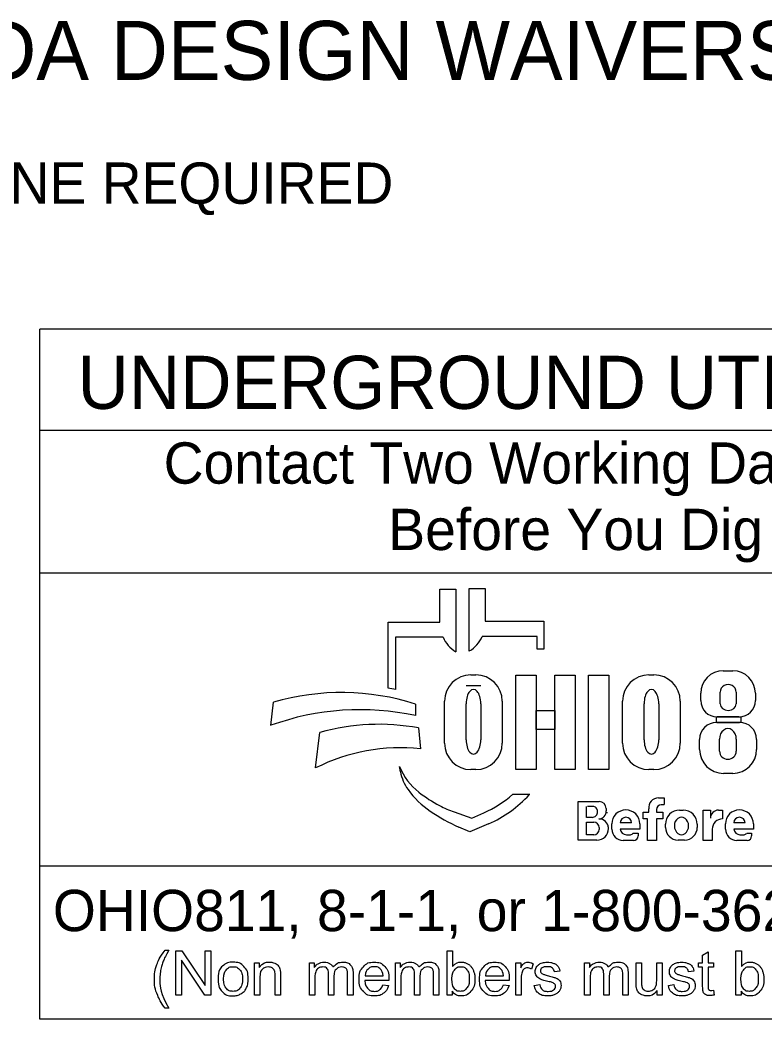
# Model space of a CAD drawing. Extents: x 0 to 44.3, y 0 to 22.
# Drawn here: x 2.311 to 4.831, y 2.143 to 5.529 of the extents above; entities that cross this region are included whole.
import ezdxf

# ---------------------------------------------------------------- set-up
doc = ezdxf.new("R2010")
doc.units = 0
doc.layers.add('SH_Data', color=7, linetype='Continuous')
doc.layers.add('SH_Text', color=7, linetype='Continuous')

msp = doc.modelspace()

# ---------------------------------------------------------------- linework, layer by layer
at = {"layer": 'SH_Data'}
for p, q in [((2.3775, 2.1428), (2.3775, 4.4803)), ((6.6275, 4.4803), (2.3775, 4.4803)), ((2.3775, 4.1387), (6.6275, 4.1387)), ((2.3775, 3.6553), (6.6275, 3.6553)), ((6.6275, 2.6607), (2.3775, 2.6607)), ((6.6275, 2.1428), (2.3775, 2.1428))]:
    msp.add_line(p, q, dxfattribs=at)
at = {"layer": 'SH_Text'}
for p, q in [((3.7335, 3.4883), (3.7335, 3.5998)), ((3.7335, 3.5998), (3.7872, 3.5998)), ((3.7872, 3.5998), (3.7872, 3.3877)), ((3.8329, 3.39), (3.8329, 3.6021)), ((3.8329, 3.6021), (3.8865, 3.6021)), ((3.8865, 3.6021), (3.8865, 3.4906)), ((3.5576, 3.2644), (3.5576, 3.4883)), ((3.5576, 3.4883), (3.7335, 3.4883)), ((3.8865, 3.4906), (4.0857, 3.4906)), ((4.0857, 3.4906), (4.0857, 3.3968)), ((3.5828, 3.4369), (3.5828, 3.26)), ((3.7439, 3.4369), (3.5828, 3.4369)), ((4.0625, 3.4392), (3.8761, 3.4392)), ((4.0625, 3.3968), (4.0625, 3.4392)), ((4.0857, 3.3968), (4.0625, 3.3968)), ((4.6931, 3.3231), (4.7258, 3.3231)), ((3.8385, 3.3091), (3.8551, 3.3091)), ((4.4416, 3.3091), (4.4581, 3.3091)), ((3.8718, 3.2721), (3.822, 3.2721)), ((4.683, 3.2111), (4.683, 3.2504)), ((4.7371, 3.2504), (4.7371, 3.2111)), ((3.7491, 3.0776), (3.7491, 3.2196)), ((3.9445, 3.2196), (3.9445, 3.0776)), ((4.3521, 3.0776), (4.3521, 3.2196)), ((4.5476, 3.2196), (4.5476, 3.0776)), ((4.6168, 3.2225), (4.6168, 3.2468)), ((4.8022, 3.2468), (4.8022, 3.2225)), ((3.1602, 3.1381), (3.1696, 3.2162)), ((3.6509, 3.2097), (3.6509, 3.1709)), ((3.822, 3.089), (3.822, 3.2114)), ((3.8718, 3.2114), (3.8718, 3.089)), ((4.425, 3.089), (4.425, 3.2114)), ((4.4748, 3.2114), (4.4748, 3.089)), ((4.7462, 3.1665), (4.6728, 3.1665)), ((3.6608, 3.1291), (3.6671, 3.0582)), ((4.671, 3.1482), (4.7483, 3.1482)), ((3.312, 2.9936), (3.3267, 3.1137)), ((4.6131, 3.0563), (4.6131, 3.0903)), ((4.6806, 3.0503), (4.6806, 3.0912)), ((4.7374, 3.0912), (4.7374, 3.0503)), ((4.8062, 3.0903), (4.8062, 3.0563)), ((3.5997, 2.9807), (3.5967, 2.9986)), ((3.8551, 2.9882), (3.8385, 2.9882)), ((4.4581, 2.9882), (4.4416, 2.9882)), ((4.7252, 2.9753), (4.6941, 2.9753)), ((3.98, 2.9048), (4.0375, 2.9048)), ((4.2013, 2.749), (4.2013, 2.8798)), ((4.2013, 2.8798), (4.2725, 2.8798)), ((4.4739, 2.8926), (4.4934, 2.8926)), ((4.4934, 2.8926), (4.4934, 2.8696)), ((3.7816, 2.8444), (3.841, 2.8239)), ((4.2293, 2.8263), (4.2293, 2.8632)), ((4.2545, 2.8632), (4.2332, 2.8632)), ((4.2963, 2.856), (4.2963, 2.8481)), ((4.4213, 2.8212), (4.4213, 2.8442)), ((4.4213, 2.8442), (4.4406, 2.8442)), ((4.4406, 2.8442), (4.4406, 2.8546)), ((4.4667, 2.8526), (4.4667, 2.8442)), ((4.4667, 2.8442), (4.4883, 2.8442)), ((4.4934, 2.8691), (4.4832, 2.8691)), ((4.4883, 2.8442), (4.4883, 2.8212)), ((4.5451, 2.8508), (4.5573, 2.8508)), ((4.6254, 2.7478), (4.6254, 2.8505)), ((4.6254, 2.8505), (4.6499, 2.8505)), ((4.6499, 2.8505), (4.6499, 2.8237)), ((4.6772, 2.8505), (4.691, 2.8505)), ((4.691, 2.8505), (4.691, 2.8209)), ((3.841, 2.8239), (3.8821, 2.8417)), ((4.2487, 2.8263), (4.2293, 2.8263)), ((4.4362, 2.8212), (4.4213, 2.8212)), ((4.4362, 2.7478), (4.4362, 2.8212)), ((4.4883, 2.8212), (4.4667, 2.8212)), ((4.4667, 2.8212), (4.4667, 2.7478)), ((3.835, 2.7769), (3.7976, 2.7934)), ((3.8983, 2.8044), (3.835, 2.7769)), ((4.2293, 2.7669), (4.2293, 2.8097)), ((4.2293, 2.8097), (4.2548, 2.8097)), ((4.2729, 2.7916), (4.2729, 2.7853)), ((4.3043, 2.7887), (4.3043, 2.7884)), ((4.3159, 2.7858), (4.3159, 2.8042)), ((4.3824, 2.8082), (4.3439, 2.8082)), ((4.4104, 2.7866), (4.344, 2.7866)), ((4.4104, 2.8042), (4.4104, 2.7866)), ((4.4973, 2.7922), (4.4973, 2.8029)), ((4.6051, 2.8029), (4.6051, 2.7922)), ((4.6559, 2.786), (4.6559, 2.7478)), ((4.7008, 2.7858), (4.7008, 2.8042)), ((4.7674, 2.8082), (4.7288, 2.8082)), ((4.7953, 2.7866), (4.7289, 2.7866)), ((4.7953, 2.8042), (4.7953, 2.7866)), ((4.265, 2.749), (4.2013, 2.749)), ((4.2546, 2.7669), (4.2293, 2.7669)), ((4.3892, 2.7478), (4.3538, 2.7478)), ((4.3649, 2.7673), (4.379, 2.7673)), ((4.3876, 2.7729), (4.4045, 2.7729)), ((4.4045, 2.7729), (4.4045, 2.7631)), ((4.4667, 2.7478), (4.4362, 2.7478)), ((4.5623, 2.7494), (4.5401, 2.7494)), ((4.6559, 2.7478), (4.6254, 2.7478)), ((4.7742, 2.7478), (4.7388, 2.7478)), ((4.7498, 2.7673), (4.7639, 2.7673)), ((4.7725, 2.7729), (4.7894, 2.7729)), ((4.7894, 2.7729), (4.7894, 2.7631))]:
    msp.add_line(p, q, dxfattribs=at)
for points in [[(3.991, 3.3081), (4.0589, 3.3081), (4.0589, 2.9881), (3.991, 2.9881)], [(4.1231, 3.3081), (4.1911, 3.3081), (4.1911, 2.9881), (4.1231, 2.9881)], [(4.2364, 3.3081), (4.3052, 3.3081), (4.3052, 2.9881), (4.2364, 2.9881)], [(4.0589, 3.1882), (4.1231, 3.1882), (4.1231, 3.1242), (4.0589, 3.1242)], [(4.6706, 3.1665), (4.7523, 3.1665), (4.7523, 3.1481), (4.6706, 3.1481)]]:
    msp.add_lwpolyline(points, close=True, dxfattribs=at)
for points in [[(2.8021, 2.3766), (2.8153, 2.3766)], [(2.8389, 2.2239), (2.8389, 2.3741), (2.8592, 2.3741), (2.9382, 2.2561), (2.9382, 2.3741), (2.9572, 2.3741), (2.9572, 2.2239), (2.9369, 2.2239), (2.8579, 2.3419), (2.8579, 2.2239), (2.8389, 2.2239)], [(3.7743, 2.2239), (3.7573, 2.2239), (3.7573, 2.3741), (3.7757, 2.3741), (3.7757, 2.3206)], [(4.6233, 2.2558), (4.6233, 2.3185), (4.6097, 2.3185), (4.6097, 2.3328), (4.6233, 2.3328), (4.6233, 2.3597), (4.6417, 2.3708), (4.6417, 2.3328), (4.6601, 2.3328), (4.6601, 2.3185), (4.6417, 2.3185), (4.6417, 2.2547)], [(4.7534, 2.2239), (4.7363, 2.2239), (4.7363, 2.3741), (4.7548, 2.3741), (4.7548, 2.3206)], [(3.1048, 2.2239), (3.1048, 2.3328), (3.1214, 2.3328), (3.1214, 2.3173)], [(3.2912, 2.2239), (3.2912, 2.3328), (3.3077, 2.3328), (3.3077, 2.3174)], [(3.5826, 2.2239), (3.5826, 2.3328), (3.5991, 2.3328), (3.5991, 2.3174)], [(3.9904, 2.2239), (3.9904, 2.3328), (4.007, 2.3328), (4.007, 2.3163)], [(4.0495, 2.3293), (4.043, 2.3122)], [(4.1394, 2.3046), (4.1213, 2.3022)], [(4.2236, 2.2239), (4.2236, 2.3328), (4.2401, 2.3328), (4.2401, 2.3174)], [(4.3979, 2.2654), (4.3979, 2.3328), (4.4164, 2.3328), (4.4164, 2.2724)], [(4.4676, 2.2745), (4.4676, 2.3328), (4.4861, 2.3328), (4.4861, 2.2239), (4.4696, 2.2239)], [(4.594, 2.3046), (4.5759, 2.3022)], [(3.1233, 2.2833), (3.1233, 2.2239), (3.1048, 2.2239)], [(3.1932, 2.2908), (3.1932, 2.2239), (3.1748, 2.2239), (3.1748, 2.2901)], [(3.3097, 2.2803), (3.3097, 2.2239), (3.2912, 2.2239)], [(3.3743, 2.2871), (3.3743, 2.2239), (3.3559, 2.2239), (3.3559, 2.2946)], [(3.4388, 2.2986), (3.4388, 2.2239), (3.4203, 2.2239), (3.4203, 2.2924)], [(3.56, 2.2736), (3.4788, 2.2736)], [(3.4799, 2.2887), (3.5406, 2.2887)], [(3.601, 2.2803), (3.601, 2.2239), (3.5826, 2.2239)], [(3.6657, 2.2871), (3.6657, 2.2239), (3.6473, 2.2239), (3.6473, 2.2946)], [(3.7301, 2.2986), (3.7301, 2.2239), (3.7117, 2.2239), (3.7117, 2.2924)], [(3.968, 2.2736), (3.8868, 2.2736)], [(3.8879, 2.2887), (3.9486, 2.2887)], [(4.0088, 2.2809), (4.0088, 2.2239), (3.9904, 2.2239)], [(4.242, 2.2803), (4.242, 2.2239), (4.2236, 2.2239)], [(4.3067, 2.2871), (4.3067, 2.2239), (4.2883, 2.2239), (4.2883, 2.2946)], [(4.3711, 2.2986), (4.3711, 2.2239), (4.3527, 2.2239), (4.3527, 2.2924)], [(3.5404, 2.2591), (3.5595, 2.2567)], [(3.7743, 2.2375), (3.7743, 2.2239)], [(3.9484, 2.2591), (3.9675, 2.2567)], [(4.053, 2.2564), (4.0712, 2.2593)], [(4.4696, 2.2239), (4.4696, 2.24)], [(4.5076, 2.2564), (4.5258, 2.2593)], [(4.6601, 2.2404), (4.6628, 2.2241)], [(4.7534, 2.2375), (4.7534, 2.2239)], [(2.8153, 2.1798), (2.8021, 2.1798)]]:
    msp.add_lwpolyline(points, dxfattribs=at)
for centre, radius, start, end in [((3.8353, 3.4736), 0.0985, 201.9296, 240.7469), ((3.7847, 3.476), 0.0985, 299.2531, 338.0704), ((4.6931, 3.2468), 0.0763, 90, 180), ((4.7258, 3.2468), 0.0763, 0, 90), ((3.8385, 3.2196), 0.0895, 90, 180), ((3.8551, 3.2196), 0.0895, 0, 90), ((4.4416, 3.2196), 0.0895, 90, 180), ((4.4581, 3.2196), 0.0895, 0, 90), ((3.4295, 2.4554), 0.8191, 79.2074, 81.0007), ((3.3997, 2.4302), 0.8191, 72.1402, 106.3144), ((4.6728, 3.2225), 0.056, 180, 270), ((4.7462, 3.2225), 0.056, 270, 0), ((3.4628, 2.2991), 0.8919, 77.8238, 109.8274), ((3.5267, 2.4094), 0.7322, 79.44, 105.8467), ((4.671, 3.0903), 0.0579, 90, 180), ((4.7483, 3.0903), 0.0579, 0, 90), ((3.5987, 2.4262), 0.6357, 83.8248, 116.8021), ((3.8385, 3.0776), 0.0895, 180, 270), ((3.8551, 3.0776), 0.0895, 270, 0), ((4.4416, 3.0776), 0.0895, 180, 270), ((4.4581, 3.0776), 0.0895, 270, 0), ((4.6941, 3.0563), 0.081, 180, 270), ((4.7252, 3.0563), 0.081, 270, 0), ((3.7841, 3.0707), 0.2008, 201.0457, 232.5314), ((3.741, 3.0048), 0.1433, 189.6817, 216.0884), ((3.8747, 3.1022), 0.3088, 216.0884, 235.7167), ((3.9766, 3.3219), 0.5173, 232.5314, 241.794), ((3.7387, 3.1722), 0.3602, 293.4582, 312.0712), ((3.7387, 3.1722), 0.401, 293.4582, 317.8286), ((4.2725, 2.856), 0.0238, 0, 90), ((4.4739, 2.859), 0.0335, 90, 187.5187), ((4.0412, 3.3465), 0.6044, 235.7167, 246.2325), ((3.8914, 3.1631), 0.3371, 241.794, 250.9821), ((4.2487, 2.845), 0.0187, 270, 2.0582), ((4.2505, 2.8463), 0.0169, 357.8325, 90), ((4.2721, 2.8453), 0.0243, 270, 6.6529), ((4.3631, 2.8042), 0.0473, 0, 180), ((4.4832, 2.8526), 0.0165, 90, 180), ((4.5451, 2.8029), 0.0478, 90, 180), ((4.5573, 2.8029), 0.0478, 0, 90), ((4.6768, 2.8237), 0.0269, 89.2449, 180), ((4.7481, 2.8042), 0.0473, 0, 180), ((4.2722, 2.7889), 0.0321, 4.0748, 90), ((4.2827, 2.8438), 0.0175, 347.4023, 0), ((4.3632, 2.8072), 0.0193, 2.9632, 177.0368), ((4.6908, 2.786), 0.0349, 89.6033, 180), ((4.7481, 2.8072), 0.0193, 2.9632, 177.0368), ((4.2546, 2.7853), 0.0184, 270, 0), ((4.2548, 2.7916), 0.0181, 0, 90), ((4.265, 2.7884), 0.0393, 270, 0), ((4.2714, 2.7887), 0.033, 0, 11.7502), ((4.3538, 2.7858), 0.038, 180, 270), ((4.3649, 2.7883), 0.021, 184.827, 270), ((4.5401, 2.7922), 0.0428, 180, 270), ((4.5623, 2.7922), 0.0428, 270, 0), ((4.7388, 2.7858), 0.038, 180, 270), ((4.7498, 2.7883), 0.021, 184.827, 270), ((4.379, 2.7767), 0.00938, 270, 335.9979), ((4.3892, 2.7631), 0.0152, 270, 0), ((4.7639, 2.7767), 0.00938, 270, 335.9979), ((4.7742, 2.7631), 0.0152, 270, 0)]:
    msp.add_arc(centre, radius, start, end, dxfattribs=at)
for centre, major_axis, ratio, start_param, end_param in [((3.8469, 3.2114), (0, 0.0484), 0.514403, 4.712389, 7.853982), ((4.4499, 3.2114), (0, 0.0484), 0.514403, 4.712389, 7.853982), ((4.71, 3.2504), (0.0271, 0), 0.969373, 0, 3.141593), ((4.71, 3.2111), (0.0271, 0), 0.818453, 3.141593, 6.283185), ((4.709, 3.0912), (0, 0.0358), 0.794529, 4.712389, 7.853982), ((3.8469, 3.089), (0, 0.0484), 0.514403, 1.570796, 4.712389), ((4.4499, 3.089), (0, 0.0484), 0.514403, 1.570796, 4.712389), ((4.709, 3.0503), (0.0284, 0), 0.959837, 3.141593, 6.283185), ((4.5517, 2.7976), (0, 0.029), 0.832186, 4.712389, 7.853982), ((4.5517, 2.7976), (0, 0.0302), 0.797287, 1.570796, 4.712389)]:
    msp.add_ellipse(centre, major_axis=major_axis, ratio=ratio, start_param=start_param, end_param=end_param, dxfattribs=at)
for points in [[(2.8021, 2.1798), (2.7869, 2.199), (2.7763, 2.2248), (2.7657, 2.2506), (2.7657, 2.2783), (2.7657, 2.3026), (2.7736, 2.325), (2.7829, 2.3509), (2.8021, 2.3766)], [(2.8153, 2.3766), (2.8029, 2.3553), (2.7989, 2.3462), (2.7927, 2.332), (2.7891, 2.3167), (2.7847, 2.2975), (2.7847, 2.2782), (2.7847, 2.2289), (2.8153, 2.1798)], [(2.9814, 2.2783), (2.9814, 2.3085), (2.9981, 2.3231), (3.0122, 2.3352), (3.0323, 2.3352), (3.0547, 2.3352), (3.069, 2.3205), (3.0832, 2.3058), (3.0832, 2.2799), (3.0832, 2.2589), (3.0769, 2.2469), (3.0706, 2.2348), (3.0586, 2.2282), (3.0466, 2.2215), (3.0323, 2.2215), (3.0095, 2.2215), (2.9954, 2.2362), (2.9814, 2.2508), (2.9814, 2.2783)], [(3.0003, 2.2783), (3.0003, 2.2574), (3.0094, 2.247), (3.0185, 2.2366), (3.0323, 2.2366), (3.046, 2.2366), (3.0551, 2.2471), (3.0642, 2.2575), (3.0642, 2.279), (3.0642, 2.2991), (3.0551, 2.3095), (3.0459, 2.3199), (3.0323, 2.3199), (3.0185, 2.3199), (3.0094, 2.3096), (3.0003, 2.2992), (3.0003, 2.2783)], [(3.1214, 2.3173), (3.1334, 2.3352), (3.156, 2.3352), (3.1659, 2.3352), (3.1741, 2.3316), (3.1823, 2.3281), (3.1864, 2.3224), (3.1905, 2.3166), (3.1922, 2.3087), (3.1932, 2.3036), (3.1932, 2.2908)], [(3.1748, 2.2901), (3.1748, 2.3013), (3.1726, 2.3069), (3.1705, 2.3125), (3.165, 2.3158), (3.1595, 2.3191), (3.1521, 2.3191), (3.1404, 2.3191), (3.1318, 2.3117), (3.1233, 2.3042), (3.1233, 2.2833)], [(3.3077, 2.3174), (3.3128, 2.3254), (3.3214, 2.3303), (3.3299, 2.3352), (3.3407, 2.3352), (3.3528, 2.3352), (3.3606, 2.3301), (3.3683, 2.3251), (3.3715, 2.3161), (3.3844, 2.3352), (3.4051, 2.3352), (3.4213, 2.3352), (3.43, 2.3262), (3.4388, 2.3172), (3.4388, 2.2986)], [(3.3559, 2.2946), (3.3559, 2.3069), (3.3514, 2.313), (3.3469, 2.3191), (3.3366, 2.3191), (3.3288, 2.3191), (3.3222, 2.315), (3.3156, 2.311), (3.3126, 2.3031), (3.3097, 2.2952), (3.3097, 2.2803)], [(3.4203, 2.2924), (3.4203, 2.3035), (3.4185, 2.3083), (3.4168, 2.3132), (3.412, 2.3162), (3.4073, 2.3191), (3.401, 2.3191), (3.3895, 2.3191), (3.3819, 2.3115), (3.3743, 2.3039), (3.3743, 2.2871)], [(3.5595, 2.2567), (3.555, 2.24), (3.5428, 2.2307), (3.5306, 2.2215), (3.5117, 2.2215), (3.4878, 2.2215), (3.4738, 2.2362), (3.4598, 2.2509), (3.4598, 2.2774), (3.4598, 2.3049), (3.474, 2.32), (3.4881, 2.3352), (3.5106, 2.3352), (3.5324, 2.3352), (3.5463, 2.3203), (3.5601, 2.3055), (3.5601, 2.2785), (3.5601, 2.2769), (3.56, 2.2736)], [(3.5406, 2.2887), (3.5394, 2.3025), (3.5337, 2.3094), (3.5249, 2.3201), (3.5108, 2.3201), (3.4981, 2.3201), (3.4894, 2.3115), (3.4808, 2.303), (3.4799, 2.2887)], [(3.5991, 2.3174), (3.6042, 2.3254), (3.6127, 2.3303), (3.6212, 2.3352), (3.6321, 2.3352), (3.6442, 2.3352), (3.6519, 2.3301), (3.6597, 2.3251), (3.6628, 2.3161), (3.6758, 2.3352), (3.6965, 2.3352), (3.7127, 2.3352), (3.7214, 2.3262), (3.7301, 2.3172), (3.7301, 2.2986)], [(3.6473, 2.2946), (3.6473, 2.3069), (3.6428, 2.313), (3.6383, 2.3191), (3.628, 2.3191), (3.6202, 2.3191), (3.6136, 2.315), (3.607, 2.311), (3.604, 2.3031), (3.601, 2.2952), (3.601, 2.2803)], [(3.7117, 2.2924), (3.7117, 2.3035), (3.7099, 2.3083), (3.7081, 2.3132), (3.7034, 2.3162), (3.6987, 2.3191), (3.6923, 2.3191), (3.6809, 2.3191), (3.6733, 2.3115), (3.6657, 2.3039), (3.6657, 2.2871)], [(3.7741, 2.2792), (3.7741, 2.2596), (3.7794, 2.2509), (3.7881, 2.2366), (3.8029, 2.2366), (3.815, 2.2366), (3.8238, 2.2471), (3.8326, 2.2576), (3.8326, 2.2784), (3.8326, 2.2998), (3.8241, 2.3099), (3.8157, 2.3201), (3.8038, 2.3201), (3.7917, 2.3201), (3.7829, 2.3096), (3.7741, 2.299), (3.7741, 2.2792)], [(3.7757, 2.3206), (3.7874, 2.3352), (3.8055, 2.3352), (3.8155, 2.3352), (3.8245, 2.3311), (3.8335, 2.3271), (3.8392, 2.3198), (3.845, 2.3124), (3.8483, 2.3021), (3.8516, 2.2918), (3.8516, 2.28), (3.8516, 2.252), (3.8378, 2.2368), (3.8239, 2.2215), (3.8046, 2.2215), (3.7853, 2.2215), (3.7743, 2.2375)], [(3.9675, 2.2567), (3.963, 2.24), (3.9508, 2.2307), (3.9386, 2.2215), (3.9196, 2.2215), (3.8958, 2.2215), (3.8818, 2.2362), (3.8678, 2.2509), (3.8678, 2.2774), (3.8678, 2.3049), (3.882, 2.32), (3.8961, 2.3352), (3.9186, 2.3352), (3.9404, 2.3352), (3.9543, 2.3203), (3.9681, 2.3055), (3.9681, 2.2785), (3.9681, 2.2769), (3.968, 2.2736)], [(3.9486, 2.2887), (3.9474, 2.3025), (3.9417, 2.3094), (3.9328, 2.3201), (3.9188, 2.3201), (3.9061, 2.3201), (3.8974, 2.3115), (3.8888, 2.303), (3.8879, 2.2887)], [(4.007, 2.3163), (4.0133, 2.3278), (4.0187, 2.3315), (4.0241, 2.3352), (4.0305, 2.3352), (4.0398, 2.3352), (4.0495, 2.3293)], [(4.043, 2.3122), (4.0363, 2.3162), (4.0295, 2.3162), (4.0235, 2.3162), (4.0187, 2.3125), (4.0139, 2.3089), (4.0119, 2.3024), (4.0088, 2.2926), (4.0088, 2.2809)], [(4.1213, 2.3022), (4.1201, 2.3106), (4.1142, 2.3153), (4.1083, 2.3201), (4.0975, 2.3201), (4.0848, 2.3201), (4.0794, 2.3159), (4.0739, 2.3116), (4.0739, 2.306), (4.0739, 2.3024), (4.0762, 2.2995), (4.0785, 2.2966), (4.0833, 2.2946), (4.086, 2.2936), (4.0996, 2.2899), (4.1192, 2.2847), (4.1269, 2.2813), (4.1347, 2.278), (4.1391, 2.2717), (4.1435, 2.2653), (4.1435, 2.2559), (4.1435, 2.2467), (4.1381, 2.2386), (4.1327, 2.2304), (4.1226, 2.226), (4.1124, 2.2215), (4.0996, 2.2215), (4.0784, 2.2215), (4.0672, 2.2303), (4.0561, 2.2391), (4.053, 2.2564)], [(4.0712, 2.2593), (4.0727, 2.2483), (4.0798, 2.2425), (4.0868, 2.2366), (4.0995, 2.2366), (4.1122, 2.2366), (4.1184, 2.2418), (4.1245, 2.247), (4.1245, 2.254), (4.1245, 2.2602), (4.1191, 2.2638), (4.1153, 2.2663), (4.1002, 2.2701), (4.0799, 2.2752), (4.072, 2.2789), (4.0642, 2.2827), (4.0601, 2.2893), (4.0561, 2.2959), (4.0561, 2.3038), (4.0561, 2.3111), (4.0594, 2.3173), (4.0628, 2.3235), (4.0685, 2.3276), (4.0728, 2.3308), (4.0803, 2.333), (4.0877, 2.3352), (4.0962, 2.3352), (4.109, 2.3352), (4.1187, 2.3315), (4.1284, 2.3278), (4.133, 2.3215), (4.1377, 2.3152), (4.1394, 2.3046)], [(4.2401, 2.3174), (4.2452, 2.3254), (4.2537, 2.3303), (4.2622, 2.3352), (4.2731, 2.3352), (4.2852, 2.3352), (4.2929, 2.3301), (4.3007, 2.3251), (4.3038, 2.3161), (4.3168, 2.3352), (4.3375, 2.3352), (4.3537, 2.3352), (4.3624, 2.3262), (4.3711, 2.3172), (4.3711, 2.2986)], [(4.2883, 2.2946), (4.2883, 2.3069), (4.2838, 2.313), (4.2793, 2.3191), (4.269, 2.3191), (4.2612, 2.3191), (4.2546, 2.315), (4.248, 2.311), (4.245, 2.3031), (4.242, 2.2952), (4.242, 2.2803)], [(4.3527, 2.2924), (4.3527, 2.3035), (4.3509, 2.3083), (4.3491, 2.3132), (4.3444, 2.3162), (4.3397, 2.3191), (4.3333, 2.3191), (4.3219, 2.3191), (4.3143, 2.3115), (4.3067, 2.3039), (4.3067, 2.2871)], [(4.5759, 2.3022), (4.5747, 2.3106), (4.5688, 2.3153), (4.5629, 2.3201), (4.5521, 2.3201), (4.5394, 2.3201), (4.5339, 2.3159), (4.5285, 2.3116), (4.5285, 2.306), (4.5285, 2.3024), (4.5308, 2.2995), (4.533, 2.2966), (4.5378, 2.2946), (4.5406, 2.2936), (4.5542, 2.2899), (4.5737, 2.2847), (4.5815, 2.2813), (4.5893, 2.278), (4.5937, 2.2717), (4.5981, 2.2653), (4.5981, 2.2559), (4.5981, 2.2467), (4.5927, 2.2386), (4.5873, 2.2304), (4.5772, 2.226), (4.567, 2.2215), (4.5542, 2.2215), (4.5329, 2.2215), (4.5218, 2.2303), (4.5107, 2.2391), (4.5076, 2.2564)], [(4.5258, 2.2593), (4.5273, 2.2483), (4.5343, 2.2425), (4.5414, 2.2366), (4.554, 2.2366), (4.5668, 2.2366), (4.5729, 2.2418), (4.5791, 2.247), (4.5791, 2.254), (4.5791, 2.2602), (4.5736, 2.2638), (4.5698, 2.2663), (4.5548, 2.2701), (4.5345, 2.2752), (4.5266, 2.2789), (4.5188, 2.2827), (4.5147, 2.2893), (4.5107, 2.2959), (4.5107, 2.3038), (4.5107, 2.3111), (4.514, 2.3173), (4.5173, 2.3235), (4.5231, 2.3276), (4.5274, 2.3308), (4.5348, 2.333), (4.5423, 2.3352), (4.5508, 2.3352), (4.5636, 2.3352), (4.5733, 2.3315), (4.583, 2.3278), (4.5876, 2.3215), (4.5922, 2.3152), (4.594, 2.3046)], [(4.7532, 2.2792), (4.7532, 2.2596), (4.7585, 2.2509), (4.7672, 2.2366), (4.782, 2.2366), (4.7941, 2.2366), (4.8029, 2.2471), (4.8116, 2.2576), (4.8116, 2.2784), (4.8116, 2.2998), (4.8032, 2.3099), (4.7948, 2.3201), (4.7828, 2.3201), (4.7708, 2.3201), (4.762, 2.3096), (4.7532, 2.299), (4.7532, 2.2792)], [(4.7548, 2.3206), (4.7664, 2.3352), (4.7846, 2.3352), (4.7946, 2.3352), (4.8036, 2.3311), (4.8125, 2.3271), (4.8183, 2.3198), (4.8241, 2.3124), (4.8274, 2.3021), (4.8306, 2.2918), (4.8306, 2.28), (4.8306, 2.252), (4.8168, 2.2368), (4.803, 2.2215), (4.7836, 2.2215), (4.7644, 2.2215), (4.7534, 2.2375)], [(3.4788, 2.2736), (3.4799, 2.2557), (3.489, 2.2462), (3.4981, 2.2366), (3.5117, 2.2366), (3.5219, 2.2366), (3.5291, 2.242), (3.5362, 2.2473), (3.5404, 2.2591)], [(3.8868, 2.2736), (3.8879, 2.2557), (3.897, 2.2462), (3.9061, 2.2366), (3.9197, 2.2366), (3.9299, 2.2366), (3.937, 2.242), (3.9442, 2.2473), (3.9484, 2.2591)], [(4.4164, 2.2724), (4.4164, 2.258), (4.4175, 2.253), (4.4192, 2.2457), (4.4249, 2.2416), (4.4305, 2.2374), (4.4388, 2.2374), (4.4471, 2.2374), (4.4543, 2.2417), (4.4616, 2.2459), (4.4646, 2.2533), (4.4676, 2.2606), (4.4676, 2.2745)], [(4.4696, 2.24), (4.4569, 2.2215), (4.4351, 2.2215), (4.4255, 2.2215), (4.4171, 2.2252), (4.4088, 2.2289), (4.4047, 2.2345), (4.4007, 2.2401), (4.3991, 2.2482), (4.3979, 2.2536), (4.3979, 2.2654)], [(4.6628, 2.2241), (4.655, 2.2224), (4.6488, 2.2224), (4.6388, 2.2224), (4.6333, 2.2256), (4.6278, 2.2288), (4.6255, 2.234), (4.6233, 2.2392), (4.6233, 2.2558)], [(4.6417, 2.2547), (4.6417, 2.2468), (4.6427, 2.2445), (4.6436, 2.2423), (4.6458, 2.2409), (4.648, 2.2396), (4.6521, 2.2396), (4.6551, 2.2396), (4.6601, 2.2404)]]:
    msp.add_open_spline(points, degree=3, dxfattribs=at)

# ---------------------------------------------------------------- texts
for s, height, p in [('ADA DESIGN WAIVERS', 0.2, (1.9944, 5.3256)), ('NONE REQUIRED', 0.14, (1.9944, 4.9056)), ('UNDERGROUND UTILITIES', 0.18, (2.5057, 4.2106)), ('Contact Two Working Days', 0.14, (2.7972, 3.9571)), ('Before You Dig', 0.14, (3.5583, 3.7321)), ('OHIO811, 8-1-1, or 1-800-362-2764', 0.14, (2.422, 2.4406))]:
    msp.add_text(s, height=height, dxfattribs=at).set_placement(p)

doc.saveas('drawing.dxf')
